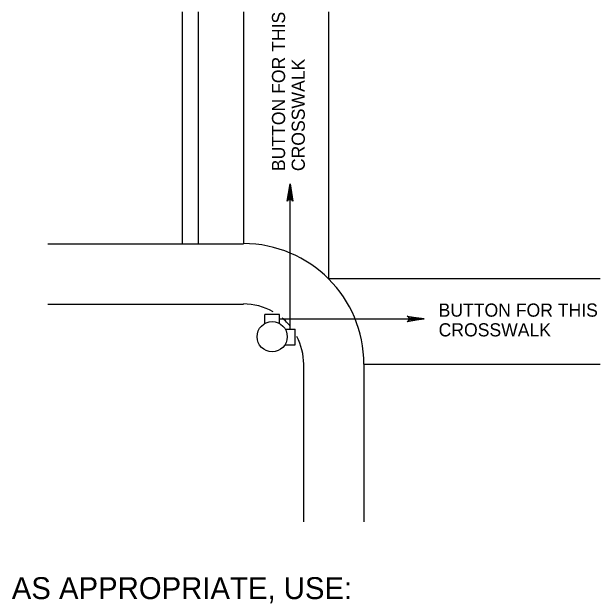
# Model space of a CAD drawing. Extents: x -344 to 940, y 22 to 1233.
# Drawn here: x -343.8 to -209.5, y 1001 to 1135.8 of the extents above; entities that cross this region are included whole.
import ezdxf

# ---------------------------------------------------------------- set-up
doc = ezdxf.new("R2010")
doc.units = 0
doc.layers.add('2', color=7, linetype='Continuous')
doc.layers.add('3', color=7, linetype='Continuous')

# ---------------------------------------------------------------- blocks, each defined once
blk = doc.blocks.new('RARROW')
at = {"layer": '3'}
blk.add_lwpolyline([(-2.937125, 0.36875), (-2.82775, 0.156125), (0, 0), (-2.937125, 0.36875), (-3.08775, 0.497625), (0, 0), (-2.8255, -0.13975), (-2.928625, -0.350125), (0, 0), (-3.08775, -0.490625), (-2.928625, -0.350125)], dxfattribs=at)

msp = doc.modelspace()

# ---------------------------------------------------------------- linework, layer by layer
at = {"layer": '2'}
for p, q in [((-304.92, 1135.83), (-304.92, 1082.95)), ((-301.29, 1135.83), (-301.29, 1082.95)), ((-290.92, 1135.83), (-290.92, 1082.95)), ((-271.54, 1135.83), (-271.54, 1074.95)), ((-280.29, 1063.45), (-280.29, 1096.58)), ((-335.54, 1082.95), (-290.92, 1082.95)), ((-209.54, 1074.95), (-271.54, 1074.95)), ((-335.54, 1069.2), (-290.92, 1069.2)), ((-286.04, 1064.7), (-286.04, 1066.83)), ((-282.67, 1066.83), (-286.04, 1066.83)), ((-282.67, 1064.7), (-282.67, 1066.83)), ((-282.67, 1065.83), (-249.67, 1065.83)), ((-281.42, 1063.45), (-279.17, 1063.45)), ((-279.17, 1059.95), (-279.17, 1063.45)), ((-281.42, 1059.95), (-279.17, 1059.95)), ((-277.17, 1019.58), (-277.17, 1055.45)), ((-209.54, 1055.45), (-263.42, 1055.45)), ((-263.42, 1019.58), (-263.42, 1055.45))]:
    msp.add_line(p, q, dxfattribs=at)
msp.add_circle((-284.38, 1061.76), 3.44, dxfattribs=at)
for radius, start, end in [(27.5, 0, 90), (13.75, 60.5288, 90), (13.75, 38.8901, 50.0196), (13.75, 0, 27.4857)]:
    msp.add_arc((-290.94, 1055.49), radius, start, end, dxfattribs=at)

# ---------------------------------------------------------------- block references
at = {"layer": '2', "xscale": 1.2574347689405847, "yscale": 1.3092961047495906, "rotation": 89.99999999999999}
msp.add_blockref('RARROW', (-280.29, 1096.58), dxfattribs=at)
at = {"layer": '2', "xscale": 1.2574347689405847, "yscale": 1.3092961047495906}
msp.add_blockref('RARROW', (-249.67, 1065.83), dxfattribs=at)

# ---------------------------------------------------------------- texts
at = {"layer": '2'}
for s, p in [('BUTTON FOR THIS', (-281.43, 1099.51)), ('CROSSWALK', (-276.93, 1099.51))]:
    msp.add_text(s, height=3, rotation=90, dxfattribs=at).set_placement(p)
for s, height, p in [('BUTTON FOR THIS', 3, (-246.4, 1066.33)), ('CROSSWALK', 3, (-246.4, 1061.83)), ('AS APPROPRIATE, USE:', 5, (-343.79, 1001.95))]:
    msp.add_text(s, height=height, dxfattribs=at).set_placement(p)

doc.saveas('drawing.dxf')
